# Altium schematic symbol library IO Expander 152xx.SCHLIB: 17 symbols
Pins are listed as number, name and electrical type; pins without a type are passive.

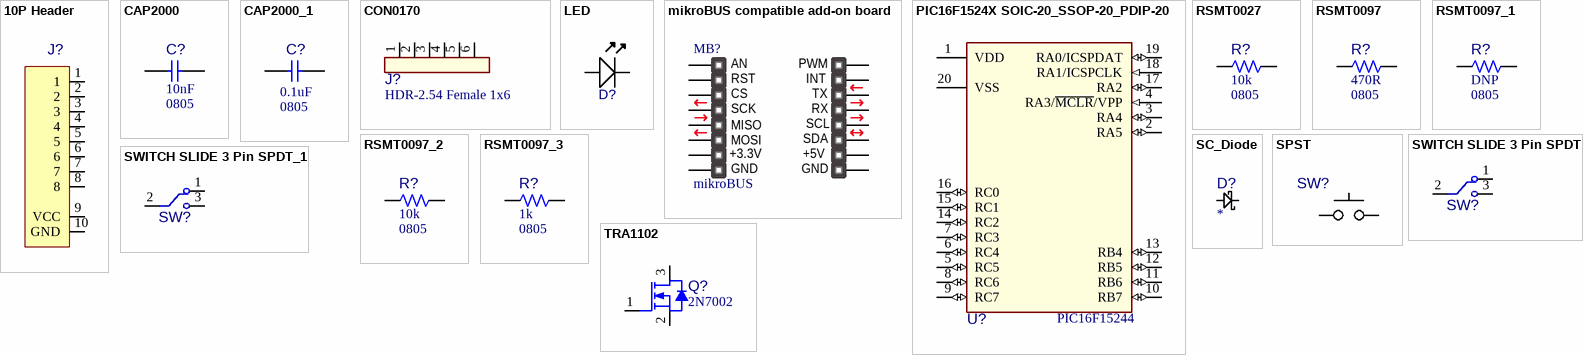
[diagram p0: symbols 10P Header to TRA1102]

## 10P Header
designator J?  (value not drawn)
pins: 1, 2, 3, 4, 5, 6, 7, 8, 9 VCC, 10 GND

## CAP2000
designator C?, comment value 10nF  Package: 0805  (hidden comment: Capacitor NP)
Manufacturer 1: Murata Electronics North America; Manufacturer Part Number 1: GRM21BR61A476ME15L; MCHP-ID: CAP2000; Voltage: 10V; Description_: CAP CER 47uF 10V 20% X5R 0805; Dev Tools Status: Production; Tolerance: 20%; Temperature Coefficient: X5R; ESR: 0.3R; Type: Ceramic; Owner: Dragos Danaila; Populated: YES
footprint RES_C_0805
pins: 1, 2
1 alternate drawing of the same symbol

## CAP2000_1
designator C?, comment value 0.1uF  Package: 0805  (hidden comment: Capacitor NP)
Manufacturer 1: Murata Electronics North America; Manufacturer Part Number 1: GRM21BR61A476ME15L; MCHP-ID: CAP2000; Voltage: 10V; Description_: CAP CER 47uF 10V 20% X5R 0805; Dev Tools Status: Production; Tolerance: 20%; Temperature Coefficient: X5R; ESR: 0.3R; Type: Ceramic; Owner: Dragos Danaila; Populated: YES
footprint RES_C_0805
pins: 1, 2
1 alternate drawing of the same symbol

## CON0170
designator J?, comment value HDR-2.54 Female 1x6  (hidden comment: Header 1x6)
Manufacturer 1: Sullins; Manufacturer Part Number 1: PPPC061LGBN-RC; MCHP-ID: CON0170; Description_: CON HDR-2.54 Female 1x6 Gold TH R/A; Dev Tools Status: Production; Owner: Ana Margeruseanu; Current: 3A; Populated: YES
footprint HDR_F_2.54_1x6_RA
pins: 1, 2, 3, 4, 5, 6
5 alternate drawings of the same symbol

## LED
designator D?  (value not drawn)
footprint 0805 LED Package (0805 Package for LED)
pins: Anode, Cathode

## mikroBUS compatible add-on board
designator MB?, comment mikroBUS  (no BOM)
mikroBUS compatible add-on board
footprint mikroBUS - Large
footprint mikroBUS - Midi
footprint mikroBUS - Mini
pins: 1 AN, 2 RST, 3 CS, 4 SCK, 5 MISO, 6 MOSI, 7 3.3V, 8 GND, 9 GND, 10 5V, 11 SDA, 12 SCL, 13 TX, 14 RX, 15 INT, 16 PWM

## PIC16F1524X SOIC-20_SSOP-20_PDIP-20
designator U?, comment PIC16F15244
PIC16F1524X SOIC-20_SSOP-20_PDIP-20
footprint SSOP-20_P0.65 (SOP, 20-Leads, Body 7.5x5.6mm (max), Pitch 0.65mm, IPC Medium Density)
pins: 1 VDD (power), 2 RA5 (io), 3 RA4 (io), 4 RA3/~{MCLR}/VPP (in), 5 RC5 (io), 6 RC4 (io), 7 RC3 (io), 8 RC6 (io), 9 RC7 (io), 10 RB7 (io), 11 RB6 (io), 12 RB5 (io), 13 RB4 (io), 14 RC2 (io), 15 RC1 (io), 16 RC0 (io), 17 RA2 (io), 18 RA1/ICSPCLK (in), 19 RA0/ICSPDAT (io), 20 VSS (power)
2 alternate drawings of the same symbol

## RSMT0027
designator R?, comment value 10k  Package: 0805  (hidden comment: Resistor)
Manufacturer 1: Panasonic; Manufacturer Part Number 1: ERJ-6GEYJ103V; MCHP-ID: RSMT0027; Tolerance: 5%; Description_: RES TKF 10k 5% 1/8W SMD 0805; Dev Tools Status: Production; Voltage: 150V; Temperature Coefficient: 100ppm/C; Power: 1/8W; Populated: Yes
footprint RES_C_0805
pins: 1, 2

## RSMT0097
designator R?, comment value 470R  Package: 0805  (hidden comment: Resistor)
Manufacturer 1: Panasonic; Manufacturer Part Number 1: ERJ-6GEYJ471V; MCHP-ID: RSMT0097; Tolerance: 5%; Description_: RES TKF 470R 5% 1/8W SMD 0805; Dev Tools Status: Production; Voltage: 150V; Temperature Coefficient: 100ppm/C; Power: 1/8W; Populated: Yes
footprint RES_C_0805
pins: 1, 2

## RSMT0097_1
designator R?, comment value DNP  Package: 0805  (hidden comment: Resistor)
Manufacturer 1: Panasonic; Manufacturer Part Number 1: ERJ-6GEYJ471V; MCHP-ID: RSMT0097; Tolerance: 5%; Description_: RES TKF 470R 5% 1/8W SMD 0805; Dev Tools Status: Production; Voltage: 150V; Temperature Coefficient: 100ppm/C; Power: 1/8W; Populated: Yes
footprint RES_C_0805
pins: 1, 2

## RSMT0097_2
designator R?, comment value 10k  Package: 0805  (hidden comment: Resistor)
Manufacturer 1: Panasonic; Manufacturer Part Number 1: ERJ-6GEYJ471V; MCHP-ID: RSMT0097; Tolerance: 5%; Description_: RES TKF 470R 5% 1/8W SMD 0805; Dev Tools Status: Production; Voltage: 150V; Temperature Coefficient: 100ppm/C; Power: 1/8W; Populated: Yes
footprint RES_C_0805
pins: 1, 2

## RSMT0097_3
designator R?, comment value 1k  Package: 0805  (hidden comment: Resistor)
Manufacturer 1: Panasonic; Manufacturer Part Number 1: ERJ-6GEYJ471V; MCHP-ID: RSMT0097; Tolerance: 5%; Description_: RES TKF 470R 5% 1/8W SMD 0805; Dev Tools Status: Production; Voltage: 150V; Temperature Coefficient: 100ppm/C; Power: 1/8W; Populated: Yes
footprint RES_C_0805
pins: 1, 2

## SC_Diode
designator D?
Schottky Diode
pins: Anode, Cathode

## SPST
designator SW?, comment SPST Switch  (value not drawn)
pins: 1, 2

## SWITCH SLIDE 3 Pin SPDT
designator SW?  (value not drawn)
footprint PCBComponent_1
footprint 3-Pad Select 0805 (Chip Resistor, 2-Leads, Body 2.0x1.3mm, IPC Medium Density)
pins: 1, 2, 3
2 alternate drawings of the same symbol

## SWITCH SLIDE 3 Pin SPDT_1
designator SW?, comment SMD Power Select  (value not drawn)
footprint 3-Pad Select 0805 (Chip Resistor, 2-Leads, Body 2.0x1.3mm, IPC Medium Density)
pins: 1, 2, 3
2 alternate drawings of the same symbol

## TRA1102
designator Q?, comment value 2N7002  (hidden comment: Transistor MOS-N GSD)
Transistor MOS; Manufacturer 1: Diodes Inc; Manufacturer Part Number 1: 2N7002-7-F; MCHP-ID: TRA1102; Description_: TRANS FET N-CH 2N7002-7-F 60V 170mA 370mW SOT-23-3; Dev Tools Status: Production; Type: FET; Current: 170mA; Drain to Source Voltage: 60V; Gate to Source Voltage: 20V; Power: 370mW; Owner: Adrian M (M91404); Populated: YES
footprint SOT-23-3
pins: 1 G, 2 S, 3 D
